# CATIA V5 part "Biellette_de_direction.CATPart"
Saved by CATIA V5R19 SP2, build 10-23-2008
Part number: Biellette_de_direction
Bounding box of the stored display mesh (mm): x 132 to 210, y -778 to -670.002, z -8 to 8
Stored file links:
  G:\EU_thinkMotion\CFAO_2010\MMS_groupe3\MMS_groupe3\pmayet\pmayet_assemblage_animation\pmayet_assemblage_animation\Biellette_de_direction.CATPart
  G:\EU_thinkMotion\CFAO_2010\MMS_groupe3\MMS_groupe3\pmayet\pmayet_assemblage_animation\pmayet_assemblage_animation\pmayet_assemblage_animation.CATProduct
  G:\EU_thinkMotion\CFAO_2010\MMS_groupe3\MMS_groupe3\pmayet\pmayet_assemblage_animation\pmayet_assemblage_animation\Squelette_biellette_de_direction.CATPart
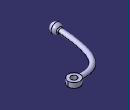
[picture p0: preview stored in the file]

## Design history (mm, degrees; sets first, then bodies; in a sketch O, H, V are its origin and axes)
Parameters
  `Rayon_sphère_biellette` = 8 mm
  Rayon_bout_biellette = 5 mm
  Rayon_tube = 4 mm
Set1
  Plane1: linked copy from another document
  Point1: linked copy from another document
  Plane2 to Plane4: linked copy from another document
  Point2: linked copy from another document
  Plane5: linked copy from another document
Body1 (main body)
  Sketch1 on Plane1, origin (0, 0, 0), H (1, 0, 0), V (0, 1, 0)
    circle A1 centre (140, -770) radius 8
    point P1 (140, -770)
    reference projected point E1 (140, -770) from Point1
    distance P1 A1 = 8 {= `Rayon_sphère_biellette`}
    coincidence: P1 E1
  Sketch2 on Plane2, origin (140, 0, 0), H (0, 1, 0), V (0, 0, 1)
    arc A1 centre (-770, 0) radius 8 from (-770, -8) to (-770, 8) ccw
    point P1 (-770, 0)
    point P2 (-770, -8)
    point P3 (-770, 8)
    reference projected point E1 (-770, 0) from Point1
    reference intersected line E2 through (-770, 0) direction (0, 1) from Plane3
    reference intersected line E3 through (-770, 0) direction (0, 1) from Plane3
    line L1 (-770, 8) -> (-770, -8)
    point P4 (-770, 8)
    point P5 (-770, -8)
    reference intersected line E4 through (-770, 0) direction (0, 1) from Plane3
    reference intersected line E5 through (-770, 0) direction (0, 1) from Plane3
    radius A1 = 8 {= `Rayon_sphère_biellette`}
    distance E2 P2 = 0
    distance P3 E3 = 0
    distance E5 L1 = 0
    distance P2 P5 = 0
    distance P4 P3 = 0
    coincidence: P1 E1
    vertical: L1 V
    parallelism: E4 L1
  Rib1: profile Sketch2, centre curve Sketch1
  Sketch3 on Plane3, origin (0, -770, 0), H (-1, 0, 0), V (0, 0, 1)
    circle A1 centre (-140, 0) radius 4
    point P1 (-140, 0)
    reference projected point E1 (-140, 0) from Point1
    distance A1 P1 = 4 {= Rayon_tube}
    coincidence: P1 E1
  Sketch4 on Plane1, origin (0, 0, 0), H (1, 0, 0), V (0, 1, 0)
    spline S1 through (140, -770) (145.7908, -721.662) (159.8586, -689.8444) (195, -680)
    reference intersected line E1 through (0, -680) direction (-1, 0) from Plane4
    reference projected point E2 (200, -680) from Point2
    reference intersected line E3 through (0, -770) direction (-1, 0) from Plane3
    reference intersected line E4 through (140, 0) direction (0, 1) from Plane2
    point P1 (195, -680)
    point P2 (140, -770)
    distance E1 P1 = 0
    distance P1 E2 = 5 {= Rayon_bout_biellette}
    distance E3 P2 = 0
    distance E4 P2 = 0
  Rib2: profile Sketch3, centre curve Sketch4
  Fillet1: radius 2.5, on edge [face of Rib1 | face of Rib2]
  Sketch5 on Plane1, origin (0, 0, 0), H (1, 0, 0), V (0, 1, 0)
    circle A1 centre (200, -680) radius 10
    point P1 (200, -680)
    reference projected point E1 (200, -680) from Point2
    distance P1 A1 = 10 {= Rayon_bout_biellette *2}
    coincidence: P1 E1
  Pad1: profile Sketch5, direction (0, 0, 1), length 4 {= Rayon_tube}, mirrored extent
  Sketch6 on Plane5, origin (0, 0, 0), H (1, 0, 0), V (0, 1, 0)
    circle A1 centre (200, -680) radius 5
    point P1 (200, -680)
    reference projected point E1 (200, -680) from Point2
    distance P1 A1 = 5 {= Rayon_bout_biellette}
    coincidence: P1 E1
  Pocket1: profile Sketch6, direction (0, 0, -1), length 4 {= Rayon_tube}, mirrored extent
Relations
  Sketch4.distance(E3 P2) = `Rayon_sphère_biellette` (deactivated)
